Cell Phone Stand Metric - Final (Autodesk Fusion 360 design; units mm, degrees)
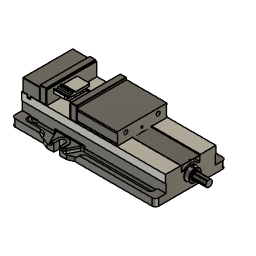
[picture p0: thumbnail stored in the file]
description: HaasClamp
derived_base_feature "Derived Base Feature" bodies "Stand Body"
align "Align1"
base_feature "Base Feature1"
base_feature "Base Feature1"
base_feature "Base Feature1"
base_feature "Base Feature1"
base_feature "Base Feature1"
base_feature "Base Feature1"
base_feature "Base Feature1"
base_feature "Base Feature1"
base_feature "Base Feature1"
base_feature "Base Feature1"
as_built_joint "As-built1"
as_built_joint "As-built2"
as_built_joint "As-built3"
joint_origin "JointOrigin1" OffsetX 0 OffsetY 0 OffsetZ 0 AngleZ 0
joint "Assemble1" alignAngle 180 alignOffsetX 0 alignOffsetY 0 alignOffsetZ 0 (= "jaw_width_haas_050002") SlideMaximum 22.5 SlideMinimum 0
position "Position1"
sketch "Sketch1" plane through (0, -72.5, 0) normal (0, -1, 0) x axis (1, 0, 0)
  line L1 (75, 73) -> (-75, 73)
  line L2 (76, 74) -> (75, 73)
  line L3 (76, 116.5) -> (76, 74)
  line L4 (75, 117.5) -> (76, 116.5)
  line L5 (-75, 117.5) -> (75, 117.5)
  line L6 (-76, 116.5) -> (-75, 117.5)
  line L7 (-76, 74) -> (-76, 116.5)
  line L8 (-75, 73) -> (-76, 74)
  line L9 (76.4, 114.275) -> (-76, 114.275)
  line L10 (76.4, 73) -> (76.4, 114.275)
  line L11 (-76, 73) -> (76.4, 73)
  line L12 (-76, 114.275) -> (-76, 73)
  circle C1 centre (49.21, 96.8) radius 11
  circle C2 centre (-49.21, 96.8) radius 11
  point P14 (76.4, 73)
  point P12 (-76, 114.275)
  point P13 (76.4, 114.275)
  horizontal L9
  vertical L10
  horizontal L11
  vertical L12
  coincident L1 P14
  coincident L7 P12
  dimension "d16" distance P12 P13 = 152.4
  dimension "d17" distance P13 P14 = 41.275
place_component sketch "Sketch1"
extrude "Extrude1" new body sketch "Sketch1" profile of L1 L2 L3 L7 L8 C1 C2 L9 L11 L12 along normal blind 3.175
place_component sketch "Sketch1"
extrude "Extrude1" sketch "Sketch1" profile of L1 L2 L3 L7 L8 C1 C2 L9 L11 L12 blind -3.175
as_built_joint "As-built5"
as_built_joint "As-built6"
sketch "Sketch1" plane through (0, 0, 0) normal (0, 0, -1) x axis (1, 0, 0)
  line L1 (16.5, -37.5) -> (-16.5, -37.5)
  line L2 (20, 34) -> (20, -34)
  line L3 (-16.5, 37.5) -> (16.5, 37.5)
  line L4 (-20, -34) -> (-20, 34)
  line L5 (-38.1, -40) -> (38.1, -40)
  line L6 (-38.1, 40) -> (-38.1, -40)
  line L7 (38.1, 40) -> (-38.1, 40)
  line L8 (38.1, -40) -> (38.1, 40)
  line L9 (-38.1, 40) -> (38.1, -40)
  line L10 (38.1, 40) -> (-38.1, -40)
  arc A1 centre (-16.5, -34) radius 3.5 clockwise from (-16.5, -37.5) to (-20, -34)
  arc A2 centre (16.5, -34) radius 3.5 clockwise from (20, -34) to (16.5, -37.5)
  arc A3 centre (16.5, 34) radius 3.5 clockwise from (16.5, 37.5) to (20, 34)
  arc A4 centre (-16.5, 34) radius 3.5 clockwise from (-20, 34) to (-16.5, 37.5)
  point P18 (0, 0)
  point P1 (0, 0)
  point P16 (-38.1, 40)
  point P17 (38.1, 40)
  point P15 (-38.1, -40)
  horizontal L5
  perpendicular L5 L6
  parallel L5 L7
  parallel L6 L8
  coincident L9 P18
  coincident L10 P18
  coincident P1 P18
  dimension "d1" distance P16 P17 = 76.2
  dimension "d2" distance P15 P16 = 80
extrude "Extrude1" new body sketch "Sketch1" profile of A1 L1 A2 L2 A3 L3 A4 L4 L5 L6 L7 L8 against normal blind 10 bodies "Stock"
position "Position1"
ground "Pin"
position "Position2"
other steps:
create_component "CreateComponent1"
create_component "CreateComponent2"
create_component "CreateComponent3"
create_component "CreateComponent4"
create_component "CreateComponent5"
create_component "CreateComponent6"
create_component "CreateComponent7"
create_component "CreateComponent8"
create_component "CreateComponent9"
create_component "CreateComponent10"
joint_origin "JointOrigin10"
joint_origin "JointOrigin11"
create_component "CreateComponent11" sketch "Sketch1"
create_component "CreateComponent12" sketch "Sketch1"
create_component "CreateComponent1"
named bodies: "Stand Body", "Stock"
